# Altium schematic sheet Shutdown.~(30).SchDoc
size A4
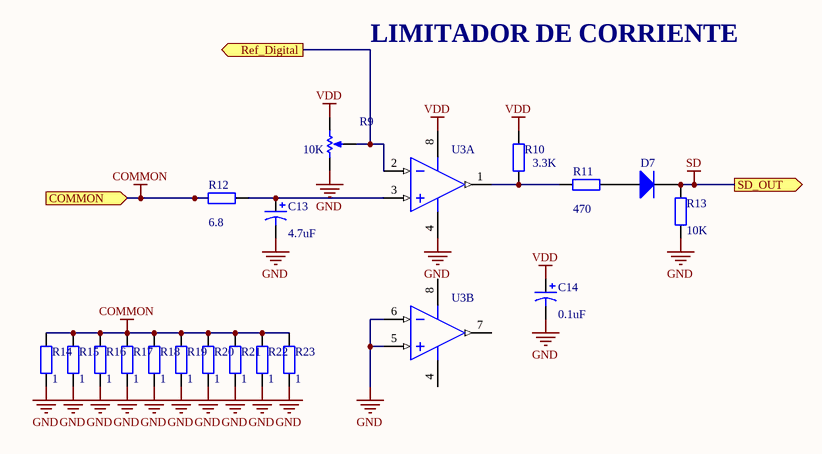
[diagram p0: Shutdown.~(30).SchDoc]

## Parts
C13  value 4.7uF  [CAPPR2.5-6.3X5]  (hidden comment: Cap Pol1)
C14  value 0.1uF  [CAPPR2.5-6.3X5]  (hidden comment: Cap Pol1)
D7  Diode  [DO-204AL]  (value not drawn)
R9  value 10K  [VR5]  (hidden comment: RPot)
R10  value 3.3K  [AXIAL-0.3]  (hidden comment: Res2)
R11  value 470  [AXIAL-0.3]  (hidden comment: Res2)
R12  value 6.8  [AXIAL-0.3]  (hidden comment: Res2)
R13  value 10K  [AXIAL-0.3]  (hidden comment: Res2)
R14  value 1  [AXIAL-0.4]  (hidden comment: Res2)
R15  value 1  [AXIAL-0.4]  (hidden comment: Res2)
R16  value 1  [AXIAL-0.4]  (hidden comment: Res2)
R17  value 1  [AXIAL-0.4]  (hidden comment: Res2)
R18  value 1  [AXIAL-0.4]  (hidden comment: Res2)
R19  value 1  [AXIAL-0.4]  (hidden comment: Res2)
R20  value 1  [AXIAL-0.4]  (hidden comment: Res2)
R21  value 1  [AXIAL-0.4]  (hidden comment: Res2)
R22  value 1  [AXIAL-0.4]  (hidden comment: Res2)
R23  value 1  [AXIAL-0.4]  (hidden comment: Res2)
U3  LM393N  [626-05]  (value not drawn)  (parts A,B of 2)

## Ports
COMMON (in), Ref_Digital (out), SD_OUT (out)

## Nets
COMMON: R12.1 R14.2 R15.2 R16.2 R17.2 R18.2 R19.2 R20.2 R21.2 R22.2 R23.2 ; port COMMON
GND: C13.2 C14.2 R9.1(TOP) R13.1 R14.1 R15.1 R16.1 R17.1 R18.1 R19.1 R20.1 R21.1 R22.1 R23.1 U3.4(GND) U3.5(IN+) U3.6(IN-)
SD: D7.2(K) R13.2 ; port SD_OUT
VDD: C14.1 R9.2(BOT) R10.2 U3.8(V+)
Ref_Digital: R9.3(TAP) U3.2(IN-) ; port Ref_Digital
NetC13_1: C13.1 R12.2 U3.3(IN+)
NetD7_1: D7.1(A) R11.2
NetR10_1: R10.1 R11.1 U3.1(OUT)

Not connected (* = marked no-connect by the designer): U3 7(OUT)

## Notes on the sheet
- LIMITADOR DE CORRIENTE

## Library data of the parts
C13 = Cap Pol1: Polarized 16V
C14 = Cap Pol1: Polarized Capacitor (Radial)
D7 = Diode: 1n4148
R9 = RPot: Potenciomentro multivuelta; Sim Note: Enter the Resistance value and the set point into parameter fields.; Set Position: 0.5
R10-R13 = Res2: metal film 1/2 W
R14-R23 = Res2: metal film 1W
U3 = LM393N: Dual Comparator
